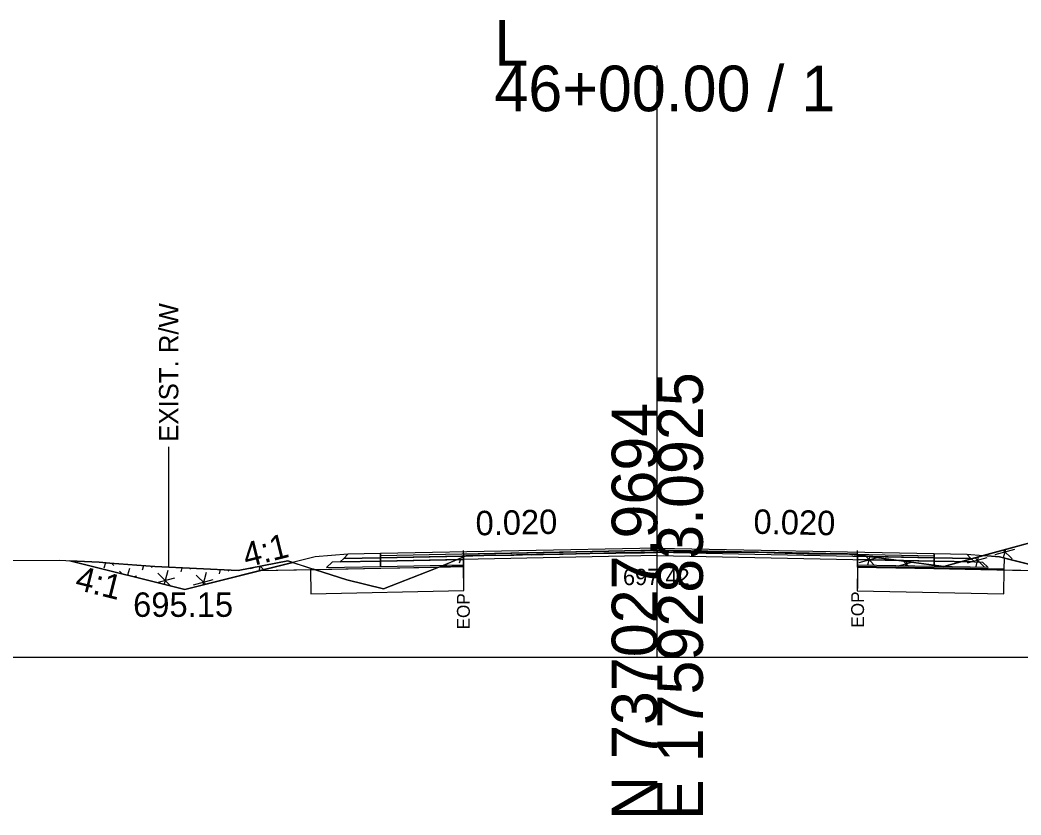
# Model space of a CAD drawing. Extents: x -26 to 4303, y -10 to 9577.
# Drawn here: x 3110.9 to 3172.3, y 5990.3 to 6039.1 of the extents above; entities that cross this region are included whole.
import ezdxf

# ---------------------------------------------------------------- set-up
doc = ezdxf.new("R2010")
doc.units = 0
for name, color, linetype in [('Exist CMT Pavement', 7, 'Continuous'), ('Old_Level_2', 7, 'Continuous'), ('Pattern 3', 7, 'Continuous'), ('Prop CMT Conc Surface', 7, 'Continuous'), ('Prop CMT Concrete Structures', 7, 'Continuous'), ('Prop CMT Pvmt Course 1', 7, 'Continuous'), ('Prop CMT Pvmt Course 1 CG', 7, 'Continuous'), ('Prop CMT Pvmt Course 2', 7, 'Continuous'), ('Prop CMT Pvmt Course 2 Wedge', 7, 'Continuous'), ('Prop CMT Pvmt Course 3', 7, 'Continuous'), ('Prop CMT Pvmt Surface', 7, 'Continuous'), ('Prop CMT Pvmt Surface Shoulder', 7, 'Continuous'), ('Prop CMT Pvmt Wedge Surface 1', 7, 'Continuous'), ('Prop CMT Pvmt Wedge Surface 2', 7, 'Continuous'), ('Prop CMT Pvmt Wedge Surface 3', 7, 'Continuous'), ('Prop CMT Shld Paved Course 1', 7, 'Continuous'), ('Prop CMT Shld Paved Course 2', 7, 'Continuous'), ('Prop CMT Shld Paved Course 3', 7, 'Continuous'), ('Prop CMT Slope Grass', 7, 'Continuous'), ('Prop CMT Subgrade Earthwork', 7, 'Continuous'), ('Prop Road Sect_ Recs - UC Shallow (Outline)', 7, 'Continuous'), ('Prop Shade Light', 7, 'Continuous'), ('Prop XS DDE Elevations', 7, 'Continuous'), ('Prop XS Ditch Standard Text', 7, 'Continuous'), ('Prop XS Hydro Elevations', 7, 'Continuous'), ('Prop XS SE Text', 7, 'Continuous'), ('Prop XS Side Slope Text', 7, 'Continuous'), ('Prop XS Wedging', 7, 'Continuous'), ('Scratch_Level_2', 7, 'Continuous'), ('Scratch_Level_9', 7, 'Continuous')]:
    doc.layers.add(name, color=color, linetype=linetype)

msp = doc.modelspace()

# ---------------------------------------------------------------- linework, layer by layer
at = {"layer": 'Exist CMT Pavement'}
for points in [[(3150, 6006.691), (3133, 6006.351)], [(3150, 6006.691), (3167, 6006.351)]]:
    msp.add_lwpolyline(points, dxfattribs=at)
at = {"layer": 'Old_Level_2'}
for p, q in [((3150, 6000), (3150, 6036.309)), ((3150, 6000), (3150, 6036.309)), ((3000, 6000), (3150, 6000)), ((3000, 6000), (3150, 6000)), ((3150, 6000), (3300, 6000)), ((3150, 6000), (3300, 6000))]:
    msp.add_line(p, q, dxfattribs=at)
at = {"layer": 'Pattern 3'}
for p, q in [((3162.395, 6005.811), (3163.513, 6006.11)), ((3162.791, 6006.208), (3163.339, 6005.632)), ((3163.054, 6006.18), (3162.91, 6005.641)), ((3169.045, 6005.792), (3170.252, 6006.116)), ((3169.511, 6006.091), (3170.091, 6005.512)), ((3169.699, 6006.143), (3169.529, 6005.509)), ((3170.739, 6006.305), (3171.946, 6006.628)), ((3171.241, 6006.568), (3171.784, 6006.025)), ((3171.38, 6006.606), (3171.242, 6006.091)), ((3114.107, 6005.909), (3114.154, 6005.862)), ((3116.112, 6005.789), (3116.025, 6005.464)), ((3116.498, 6005.756), (3116.629, 6005.626)), ((3117.586, 6005.434), (3117.478, 6005.031)), ((3118.451, 6005.605), (3118.381, 6005.345)), ((3118.923, 6005.569), (3118.985, 6005.507)), ((3120.805, 6005.476), (3120.738, 6005.227)), ((3121.275, 6005.455), (3121.341, 6005.389)), ((3125.009, 6005.432), (3125.383, 6005.532)), ((3125.607, 6005.575), (3125.529, 6005.283)), ((3125.627, 6005.579), (3125.844, 6005.362)), ((3164.806, 6005.603), (3165.632, 6005.825)), ((3165.121, 6005.894), (3165.424, 6005.591)), ((3165.32, 6005.867), (3165.247, 6005.594)), ((3116.982, 6005.272), (3117.138, 6005.116)), ((3117.839, 6004.941), (3118.028, 6004.992)), ((3119.286, 6004.579), (3120.384, 6004.873)), ((3119.339, 6005.154), (3120.122, 6004.37)), ((3119.942, 6005.315), (3119.716, 6004.472)), ((3121.695, 6005.035), (3122.263, 6004.467)), ((3122.299, 6005.197), (3122.092, 6004.424)), ((3123.164, 6005.37), (3123.094, 6005.109)), ((3123.619, 6005.349), (3123.698, 6005.27)), ((3124.051, 6004.917), (3124.054, 6004.914)), ((3124.655, 6005.079), (3124.651, 6005.064)), ((3121.533, 6004.431), (3122.741, 6004.755))]:
    msp.add_line(p, q, dxfattribs=at)
for points in [[(3162.297, 6006.254), (3162.298, 6005.57), (3171.306, 6005.39), (3171.307, 6006.074), (3179, 6004.151), (3201.119, 6009.681), (3187.852, 6009.329), (3182.431, 6009.193), (3173.78, 6007.256), (3169.528, 6006.096), (3167.586, 6005.561), (3167.274, 6005.603), (3166.936, 6005.649), (3164.802, 6005.937), (3163.307, 6006.138), (3162.791, 6006.208), (3162.297, 6006.254)], [(3136.643, 6005.549), (3138.094, 6006.145), (3138.094, 6005.578)], [(3113.93, 6005.918), (3121, 6004.151), (3127.615, 6005.805), (3127.313, 6005.902), (3124.272, 6005.32), (3119.145, 6005.552), (3116.388, 6005.765), (3115.733, 6005.821)]]:
    msp.add_lwpolyline(points, close=True, dxfattribs=at)
at = {"layer": 'Prop CMT Conc Surface'}
for points in [[(3138.094, 6006.203), (3133, 6006.101)], [(3133, 6006.101), (3133, 6005.893)], [(3138.094, 6005.994), (3138.094, 6006.203)], [(3162.298, 6005.987), (3162.298, 6006.195)], [(3162.298, 6006.195), (3167, 6006.101)], [(3167, 6006.101), (3167, 6005.893)], [(3133, 6005.893), (3138.094, 6005.994)], [(3167, 6005.893), (3162.298, 6005.987)]]:
    msp.add_lwpolyline(points, dxfattribs=at)
at = {"layer": 'Prop CMT Concrete Structures'}
for points in [[(3133, 6006.101), (3133, 6006.351)], [(3138.094, 6006.203), (3133, 6006.101)], [(3150, 6006.566), (3138.094, 6006.328)], [(3138.094, 6006.328), (3138.094, 6006.203)], [(3150, 6006.566), (3162.298, 6006.32)], [(3162.298, 6006.32), (3162.298, 6006.195)], [(3162.298, 6006.195), (3167, 6006.101)], [(3167, 6006.101), (3167, 6006.351)]]:
    msp.add_lwpolyline(points, dxfattribs=at)
at = {"layer": 'Prop CMT Pvmt Course 1'}
for points in [[(3138.094, 6005.994), (3133, 6005.893)], [(3133, 6005.893), (3133, 6005.559)], [(3133, 6005.559), (3138.094, 6005.661)], [(3138.094, 6005.661), (3138.094, 6005.994)], [(3162.298, 6005.987), (3167, 6005.893)], [(3162.298, 6005.653), (3162.298, 6005.987)], [(3167, 6005.559), (3162.298, 6005.653)], [(3167, 6005.893), (3167, 6005.559)]]:
    msp.add_lwpolyline(points, dxfattribs=at)
at = {"layer": 'Prop CMT Pvmt Course 2'}
for points in [[(3133, 6006.351), (3131, 6006.311), (3130.745, 6006.056)], [(3130.745, 6006.056), (3133, 6006.101)], [(3133, 6006.101), (3133, 6006.351)], [(3167, 6006.351), (3169, 6006.311), (3169.255, 6006.056)], [(3167, 6006.101), (3167, 6006.351)], [(3169.255, 6006.056), (3167, 6006.101)]]:
    msp.add_lwpolyline(points, dxfattribs=at)
at = {"layer": 'Prop CMT Pvmt Course 2 Wedge'}
for points in [[(3169, 6006.311), (3171, 6006.151), (3179, 6004.151), (3201.119, 6009.681)], [(3131, 6006.311), (3129, 6006.151), (3121, 6004.151), (3113.93, 6005.918)]]:
    msp.add_lwpolyline(points, dxfattribs=at)
at = {"layer": 'Prop CMT Pvmt Course 3'}
for points in [[(3133, 6006.101), (3130.745, 6006.056), (3130.532, 6005.843)], [(3133, 6005.893), (3133, 6006.101)], [(3167, 6006.101), (3169.255, 6006.056), (3169.468, 6005.843)], [(3167, 6005.893), (3167, 6006.101)], [(3130.532, 6005.843), (3133, 6005.893)], [(3169.468, 6005.843), (3167, 6005.893)]]:
    msp.add_lwpolyline(points, dxfattribs=at)
at = {"layer": 'Prop CMT Pvmt Surface'}
for points in [[(3150, 6006.441), (3133, 6006.101)], [(3133, 6006.101), (3133, 6006.351)], [(3150, 6006.441), (3167, 6006.101)], [(3167, 6006.101), (3167, 6006.351)]]:
    msp.add_lwpolyline(points, dxfattribs=at)
at = {"layer": 'Prop CMT Pvmt Surface Shoulder'}
for points in [[(3138.095, 6006.145), (3138.246, 6006.207), (3138.665, 6006.219), (3139.353, 6006.239), (3141.194, 6006.264), (3141.716, 6006.276), (3142.584, 6006.292), (3144.217, 6006.327), (3145.016, 6006.348), (3146.718, 6006.385), (3147.448, 6006.389), (3149.219, 6006.407), (3149.394, 6006.412), (3149.777, 6006.412), (3149.998, 6006.42)], [(3149.998, 6006.42), (3150.479, 6006.435), (3151.274, 6006.433), (3151.592, 6006.433), (3151.72, 6006.431), (3152.312, 6006.432), (3154.221, 6006.443), (3154.744, 6006.444), (3156.722, 6006.424), (3157.176, 6006.406), (3159.223, 6006.336), (3161.18, 6006.34), (3161.405, 6006.341), (3161.652, 6006.338), (3162.096, 6006.271), (3162.297, 6006.254)]]:
    msp.add_lwpolyline(points, dxfattribs=at)
at = {"layer": 'Prop CMT Pvmt Wedge Surface 1'}
for p, q in [((3133.018, 6005.434), (3125.535, 6005.285)), ((3138.094, 6005.536), (3133.018, 6005.434)), ((3162.299, 6005.528), (3166.982, 6005.434)), ((3166.982, 6005.434), (3174.465, 6005.285))]:
    msp.add_line(p, q, dxfattribs=at)
for points in [[(3138.094, 6005.536), (3138.095, 6006.145)], [(3162.299, 6005.528), (3162.297, 6006.254)]]:
    msp.add_lwpolyline(points, dxfattribs=at)
at = {"layer": 'Prop CMT Pvmt Wedge Surface 2'}
for points in [[(3138.094, 6006.328), (3138.246, 6006.331), (3138.665, 6006.339), (3139.353, 6006.353), (3141.194, 6006.39), (3141.716, 6006.4), (3142.584, 6006.418), (3144.217, 6006.45), (3145.016, 6006.466), (3146.718, 6006.5), (3147.448, 6006.515), (3149.219, 6006.55), (3149.394, 6006.554), (3149.777, 6006.561), (3150, 6006.566)], [(3150, 6006.441), (3149.777, 6006.436), (3149.394, 6006.429), (3149.219, 6006.425), (3147.448, 6006.39), (3147.397, 6006.389), (3146.718, 6006.385), (3145.016, 6006.348), (3144.217, 6006.327), (3143.012, 6006.301), (3142.584, 6006.293), (3142.249, 6006.286), (3141.716, 6006.276), (3141.353, 6006.268), (3141.194, 6006.265), (3141.111, 6006.263), (3139.353, 6006.239), (3138.665, 6006.219), (3138.246, 6006.207), (3138.243, 6006.206), (3138.094, 6006.203)], [(3138.094, 6006.203), (3138.094, 6006.328)], [(3150, 6006.566), (3150, 6006.441)], [(3150, 6006.566), (3150.479, 6006.556), (3151.274, 6006.54), (3151.592, 6006.534), (3151.72, 6006.531), (3152.312, 6006.52), (3154.221, 6006.481), (3154.744, 6006.471), (3156.722, 6006.431), (3157.176, 6006.422), (3159.223, 6006.381), (3161.18, 6006.342), (3161.285, 6006.34)], [(3161.285, 6006.34), (3161.18, 6006.34), (3159.223, 6006.336), (3157.176, 6006.406), (3156.722, 6006.424), (3154.744, 6006.444), (3154.221, 6006.443), (3152.312, 6006.432), (3151.72, 6006.431), (3151.592, 6006.433), (3151.274, 6006.433), (3150.479, 6006.435), (3150.401, 6006.433), (3150, 6006.441)], [(3162.298, 6006.254), (3162.096, 6006.271), (3161.693, 6006.332)], [(3161.693, 6006.332), (3162.096, 6006.324)], [(3162.096, 6006.324), (3162.298, 6006.32)], [(3162.298, 6006.32), (3162.298, 6006.254)]]:
    msp.add_lwpolyline(points, dxfattribs=at)
at = {"layer": 'Prop CMT Pvmt Wedge Surface 3'}
for points in [[(3138.094, 6006.203), (3138.243, 6006.206)], [(3138.243, 6006.206), (3138.094, 6006.145)], [(3138.094, 6006.145), (3138.094, 6006.203)], [(3141.347, 6006.268), (3141.194, 6006.264), (3141.114, 6006.263)], [(3141.114, 6006.263), (3141.194, 6006.265)], [(3141.194, 6006.265), (3141.347, 6006.268)], [(3143.001, 6006.301), (3142.584, 6006.292), (3142.257, 6006.286)], [(3142.257, 6006.286), (3142.584, 6006.293)], [(3142.584, 6006.293), (3143.001, 6006.301)], [(3150, 6006.42), (3149.777, 6006.412), (3149.394, 6006.412), (3149.219, 6006.407), (3147.448, 6006.389), (3147.398, 6006.389)], [(3147.398, 6006.389), (3147.448, 6006.39)], [(3147.448, 6006.39), (3149.219, 6006.425), (3149.394, 6006.429), (3149.777, 6006.436), (3150, 6006.441)], [(3150, 6006.441), (3150, 6006.42)], [(3150, 6006.441), (3150.401, 6006.433)], [(3150.401, 6006.433), (3150, 6006.42)]]:
    msp.add_lwpolyline(points, dxfattribs=at)
at = {"layer": 'Prop CMT Shld Paved Course 1'}
for points in [[(3133, 6005.893), (3133, 6006.351)], [(3150, 6006.233), (3133, 6005.893)], [(3150, 6006.233), (3167, 6005.893)], [(3167, 6005.893), (3167, 6006.351)]]:
    msp.add_lwpolyline(points, dxfattribs=at)
at = {"layer": 'Prop CMT Shld Paved Course 2'}
for points in [[(3133, 6006.351), (3131, 6006.311)], [(3167, 6006.351), (3169, 6006.311)]]:
    msp.add_lwpolyline(points, dxfattribs=at)
at = {"layer": 'Prop CMT Shld Paved Course 3'}
for points in [[(3150, 6006.691), (3133, 6006.351)], [(3150, 6006.441), (3150, 6006.691)], [(3150, 6006.691), (3167, 6006.351)], [(3133, 6006.351), (3133, 6006.101)], [(3133, 6006.101), (3138.094, 6006.203)], [(3138.094, 6006.328), (3150, 6006.566)], [(3138.094, 6006.203), (3138.094, 6006.328)], [(3150, 6006.566), (3150, 6006.441), (3150, 6006.441)], [(3162.298, 6006.32), (3150, 6006.566)], [(3162.298, 6006.195), (3162.298, 6006.32)], [(3167, 6006.101), (3162.298, 6006.195)], [(3167, 6006.351), (3167, 6006.101)]]:
    msp.add_lwpolyline(points, dxfattribs=at)
at = {"layer": 'Prop CMT Slope Grass'}
msp.add_lwpolyline([(3110.282, 6005.928), (3113.287, 6005.953), (3115.733, 6005.821), (3116.388, 6005.765), (3119.145, 6005.552), (3124.272, 6005.32), (3127.313, 6005.902), (3130.929, 6004.737), (3133.192, 6004.187), (3136.39, 6005.445), (3138.246, 6006.207), (3138.665, 6006.219), (3139.353, 6006.239), (3141.194, 6006.264), (3141.716, 6006.276), (3142.584, 6006.292), (3144.217, 6006.327), (3145.016, 6006.348), (3146.718, 6006.385), (3147.448, 6006.389), (3149.394, 6006.412), (3150, 6006.42), (3150.479, 6006.435), (3151.274, 6006.433), (3151.72, 6006.431), (3152.312, 6006.432), (3154.221, 6006.443), (3154.744, 6006.444), (3156.722, 6006.424), (3157.176, 6006.406), (3159.223, 6006.336), (3161.652, 6006.338), (3162.096, 6006.271), (3162.685, 6006.222), (3167.586, 6005.561), (3173.558, 6007.206)], dxfattribs=at)
at = {"layer": 'Prop CMT Subgrade Earthwork'}
for points in [[(3133, 6005.893), (3130.532, 6005.843), (3130.032, 6005.833), (3129.692, 6005.493)], [(3129.692, 6005.493), (3133, 6005.559)], [(3133, 6005.559), (3133, 6005.893)], [(3167, 6005.893), (3169.468, 6005.843), (3169.968, 6005.833), (3170.308, 6005.493)], [(3167, 6005.559), (3167, 6005.893)], [(3170.308, 6005.493), (3167, 6005.559)]]:
    msp.add_lwpolyline(points, dxfattribs=at)
at = {"layer": 'Prop Road Sect_ Recs - UC Shallow (Outline)'}
for points in [[(3128.723, 6003.89), (3138.124, 6004.078), (3138.094, 6005.578), (3136.643, 6005.549), (3133.192, 6004.187), (3130.931, 6004.736), (3128.89, 6005.394), (3128.702, 6005.39)], [(3162.267, 6004.07), (3171.276, 6003.89), (3171.306, 6005.39), (3162.297, 6005.57)]]:
    msp.add_lwpolyline(points, close=True, dxfattribs=at)
at = {"layer": 'Prop Shade Light'}
for p, q in [((3136.643, 6005.549), (3133.192, 6004.187)), ((3138.094, 6005.578), (3136.643, 6005.549)), ((3138.124, 6004.078), (3138.094, 6005.578)), ((3162.297, 6005.57), (3162.267, 6004.07)), ((3128.89, 6005.394), (3128.703, 6005.371)), ((3128.703, 6005.371), (3128.723, 6003.89)), ((3130.931, 6004.736), (3128.89, 6005.394)), ((3171.306, 6005.39), (3170.306, 6005.41)), ((3171.276, 6003.89), (3171.306, 6005.39)), ((3133.192, 6004.187), (3130.931, 6004.736)), ((3128.723, 6003.89), (3138.124, 6004.078)), ((3162.267, 6004.07), (3171.276, 6003.89))]:
    msp.add_line(p, q, dxfattribs=at)
msp.add_lwpolyline([(3170.306, 6005.41), (3166.998, 6005.476), (3162.297, 6005.57)], dxfattribs=at)
at = {"layer": 'Prop XS DDE Elevations'}
for points in [[(3179, 6004.151), (3201.119, 6009.681), (3194.2, 6009.525), (3191.671, 6009.424), (3182.431, 6009.193), (3173.558, 6007.206), (3170.014, 6006.23), (3171, 6006.151), (3174.465, 6005.285)], [(3138.094, 6005.536), (3136.535, 6005.505), (3138.095, 6006.145)], [(3147.448, 6006.389), (3149.219, 6006.407), (3149.394, 6006.412)], [(3149.394, 6006.412), (3149.777, 6006.412), (3149.998, 6006.42)], [(3151.274, 6006.433), (3151.592, 6006.433), (3151.72, 6006.431)], [(3159.223, 6006.336), (3161.18, 6006.34), (3161.405, 6006.341), (3161.652, 6006.338)], [(3162.299, 6005.528), (3166.982, 6005.434), (3174.465, 6005.285), (3171, 6006.151), (3170.014, 6006.23), (3167.586, 6005.561), (3162.685, 6006.222), (3162.297, 6006.254)], [(3116.388, 6005.765), (3119.145, 6005.552), (3124.272, 6005.32), (3127.313, 6005.902), (3127.615, 6005.805), (3125.535, 6005.285), (3121, 6004.151), (3113.93, 6005.918), (3115.733, 6005.821)], [(3127.615, 6005.805), (3129.013, 6005.354), (3125.535, 6005.285)], [(3130.929, 6004.737), (3133.192, 6004.187), (3136.39, 6005.445), (3136.535, 6005.505), (3133.018, 6005.434), (3129.013, 6005.354)]]:
    msp.add_lwpolyline(points, close=True, dxfattribs=at)
at = {"layer": 'Prop XS Ditch Standard Text'}
for p, q in [((3120, 6012.914), (3120, 6005.513)), ((3138.094, 6006.145), (3138.094, 6004.094)), ((3162.298, 6006.254), (3162.298, 6004.204))]:
    msp.add_line(p, q, dxfattribs=at)
at = {"layer": 'Prop XS Wedging'}
for p, q in [((3138.094, 6006.145), (3138.094, 6006.549)), ((3138.095, 6006.328), (3138.095, 6006.145)), ((3138.095, 6006.145), (3138.095, 6006.145)), ((3150.002, 6006.566), (3150, 6006.566)), ((3161.393, 6006.338), (3150.002, 6006.566)), ((3162.297, 6006.32), (3161.693, 6006.332)), ((3162.297, 6006.254), (3162.297, 6006.32)), ((3162.298, 6006.254), (3162.298, 6006.553))]:
    msp.add_line(p, q, dxfattribs=at)
for points in [[(3150.002, 6006.566), (3133.002, 6006.226)], [(3150, 6006.566), (3149.998, 6006.566), (3138.095, 6006.328)], [(3138.095, 6006.145), (3138.246, 6006.207), (3138.665, 6006.219), (3139.353, 6006.239), (3141.194, 6006.264), (3141.716, 6006.276), (3142.584, 6006.292), (3144.217, 6006.327), (3145.016, 6006.348), (3146.718, 6006.385), (3147.448, 6006.389), (3149.394, 6006.412), (3150, 6006.42), (3150.479, 6006.435), (3151.274, 6006.433), (3151.72, 6006.431), (3152.312, 6006.432), (3154.221, 6006.443), (3154.744, 6006.444), (3156.722, 6006.424), (3157.176, 6006.406), (3159.223, 6006.336), (3161.393, 6006.338)], [(3149.998, 6006.566), (3166.998, 6006.226)], [(3161.693, 6006.332), (3162.096, 6006.271), (3162.297, 6006.254)], [(3162.297, 6006.254), (3162.297, 6006.254)]]:
    msp.add_lwpolyline(points, dxfattribs=at)
at = {"layer": 'Scratch_Level_2'}
msp.add_line((3137.908, 6006.012), (3137.843, 6005.772), dxfattribs=at)
at = {"layer": 'Scratch_Level_9'}
msp.add_line((3137.006, 6005.705), (3136.989, 6005.639), dxfattribs=at)

# ---------------------------------------------------------------- texts
at = {"layer": 'Old_Level_2'}
for s, p in [('L', (3140, 6036.309)), ('L', (3140, 6036.309)), ('46+00.00 / 1', (3140, 6033.509)), ('46+00.00 / 1', (3140, 6033.509))]:
    msp.add_text(s, height=2.8, dxfattribs=at).set_placement(p)
for s, p in [('E 1759283.0925', (3152.8, 5990)), ('E 1759283.0925', (3152.8, 5990)), ('N 737027.9694', (3150, 5990)), ('N 737027.9694', (3150, 5990))]:
    msp.add_text(s, height=2.8, rotation=90, dxfattribs=at).set_placement(p)
at = {"layer": 'Prop CMT Pvmt Course 1 CG'}
msp.add_text('697.42', height=1, dxfattribs=at).set_placement((3147.893, 6004.42))
at = {"layer": 'Prop XS Ditch Standard Text'}
for s, height, p in [('EXIST. R/W', 1.1811, (3120.591, 6013.216)), ('EOP', 0.7874, (3138.488, 6001.696)), ('EOP', 0.7874, (3162.692, 6001.805))]:
    msp.add_text(s, height=height, rotation=90, dxfattribs=at).set_placement(p)
at = {"layer": 'Prop XS Hydro Elevations'}
msp.add_text('695.15', height=1.5, dxfattribs=at).set_placement((3117.818, 6002.47))
at = {"layer": 'Prop XS SE Text'}
for rotation, p in [(1.14576, (3138.856, 6007.468)), (358.85424, (3155.896, 6007.573))]:
    msp.add_text('0.020', height=1.5, rotation=rotation, dxfattribs=at).set_placement(p)
at = {"layer": 'Prop XS Side Slope Text'}
for rotation, p in [(14.03624, (3124.769, 6005.49)), (345.96376, (3114.185, 6004.176))]:
    msp.add_text('4:1', height=1.5, rotation=rotation, dxfattribs=at).set_placement(p)

doc.saveas('drawing.dxf')
